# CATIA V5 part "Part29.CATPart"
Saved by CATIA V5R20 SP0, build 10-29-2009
Part number: 8PF01042WB-00-RECTO-20130117
Revision: ANY
Definition: UNKNOWN
Nomenclature: 8PF01042WB-00-RECTO-20130117
Source: Unknown
Bounding box of the stored display mesh (mm): x 1681.949 to 1881.949, y 1407.509 to 1411.509, z 0 to 10
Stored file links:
  C:\Users\Utente\Desktop\IO LAVORO\3D X SITO CF\CUMSA\3D files PF\PF 104200\Part29.CATPart
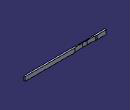
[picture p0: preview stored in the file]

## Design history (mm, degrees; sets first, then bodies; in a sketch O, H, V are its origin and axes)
Body1 "Cortar-Extruir1" (main body)
  Solid1: solid without history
